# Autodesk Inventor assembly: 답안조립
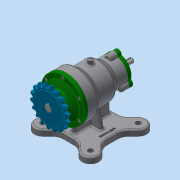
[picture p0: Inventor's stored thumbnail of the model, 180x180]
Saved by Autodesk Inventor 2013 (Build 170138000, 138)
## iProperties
Created: 2017-03
Part Number: 답안조립
Document SubType Name: Assembly
Designer: Administrator
Author: Administrator
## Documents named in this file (14)
- C:\Users\Administrator\Desktop\470307V1024\답안조립.iam
- C:\Users\Administrator\Desktop\470307V1024\본체.ipt
- C:\Users\Administrator\Desktop\470307V1024\뒤커버.ipt
- C:\Users\Administrator\Desktop\470307V1024\베어링-6200.ipt
- C:\Users\Administrator\Desktop\470307V1024\베어링-6203.ipt
- C:\Users\Administrator\Desktop\470307V1024\볼트 M4 x 12.ipt
- C:\Users\Administrator\Desktop\470307V1024\볼트 M5 x 10.ipt
- 볼트 M5 x 10.ipt
- C:\Users\Administrator\Desktop\470307V1024\스프로킷.ipt
- C:\Users\Administrator\Desktop\470307V1024\앞커버.ipt
- C:\Users\Administrator\Desktop\470307V1024\오일 실 10 20 7.ipt
- C:\Users\Administrator\Desktop\470307V1024\오일 실 17 30 8.ipt
- C:\Users\Administrator\Desktop\470307V1024\축.ipt
- C:\Users\Administrator\Desktop\470307V1024\키5x5.ipt
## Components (9 placed, 1 different names)
1. ISO 4762 M4 x 12:2
2. ISO 4762 M4 x 12:3
3. ISO 4762 M4 x 12:4
4. ISO 4762 M4 x 12:5
5. ISO 4762 M4 x 12:6
6. ISO 4762 M4 x 12:7
7. ISO 4762 M4 x 12:1
8. ISO 4762 M4 x 12:8
9. ISO 4762 M4 x 12:9
